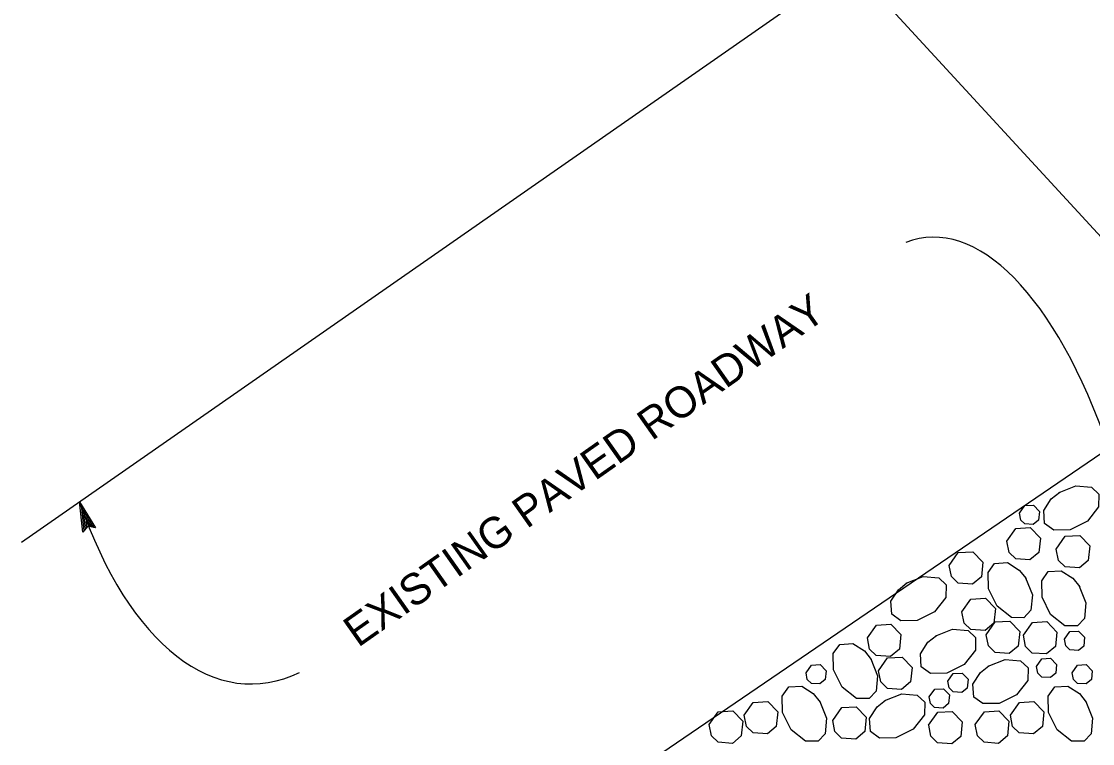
# Model space of a CAD drawing. Extents: x 6709491 to 6710959, y 1869789 to 1870763.
# Drawn here: x 6709490.8 to 6709696.9, y 1870298.5 to 1870437.5 of the extents above; entities that cross this region are included whole.
import ezdxf

# ---------------------------------------------------------------- set-up
doc = ezdxf.new("R2010")
doc.units = 0
for name, color, linetype in [('56 Stg 3 Anno', 7, 'Continuous'), ('57 Undefined', 7, 'Continuous'), ('60 Nongeo Data', 7, 'Continuous')]:
    doc.layers.add(name, color=color, linetype=linetype)

msp = doc.modelspace()

# ---------------------------------------------------------------- linework, layer by layer
at = {"layer": '56 Stg 3 Anno'}
for p, q in [((6709720.74, 1870371.76), (6709642.2, 1870457.23)), ((6709502.63, 1870339.17), (6709501.98, 1870345.03)), ((6709501.98, 1870345.03), (6709501.98, 1870345.03)), ((6709501.98, 1870345.03), (6709505.05, 1870340)), ((6709502.89, 1870339.48), (6709502.41, 1870343.78)), ((6709502.41, 1870343.77), (6709504.66, 1870340.1)), ((6709503.14, 1870339.8), (6709502.84, 1870342.52)), ((6709502.84, 1870342.52), (6709504.28, 1870340.16)), ((6709503.6, 1870340.31), (6709502.63, 1870339.17)), ((6709503.4, 1870340.07), (6709503.27, 1870341.27)), ((6709503.27, 1870341.27), (6709503.89, 1870340.26)), ((6709505.05, 1870340), (6709503.6, 1870340.31)), ((6709505.05, 1870340), (6709505.05, 1870340)), ((6709502.63, 1870339.17), (6709502.63, 1870339.17))]:
    msp.add_line(p, q, dxfattribs=at)
for centre, major_axis, ratio, start_param, end_param in [((6709673.96, 1870309.82), (9.19, -86.07), 0.406988, 2.083758, 3.252367), ((6709534.98, 1870392.41), (0, 82.45), 0.489041, 2.182883, 3.375209)]:
    msp.add_ellipse(centre, major_axis=major_axis, ratio=ratio, start_param=start_param, end_param=end_param, dxfattribs=at)
at = {"layer": '60 Nongeo Data'}
for p, q in [((6709490.8, 1870337.24), (6709770.14, 1870531.99)), ((6709495.94, 1870216.26), (6709884.38, 1870481.01))]:
    msp.add_line(p, q, dxfattribs=at)
for points in [[(6709690.41, 1870346.81), (6709693.66, 1870348.1), (6709696.65, 1870347.85), (6709698.07, 1870346.5), (6709698.03, 1870344.07), (6709695.87, 1870341.31), (6709692.54, 1870339.65), (6709689.4, 1870339.59), (6709687.63, 1870340.85), (6709687.46, 1870343.35), (6709688.9, 1870345.59), (6709690.54, 1870346.9)], [(6709682.78, 1870342.81), (6709683.83, 1870344.29), (6709685.49, 1870344.39), (6709686.65, 1870343.19), (6709686.49, 1870341.51), (6709685.46, 1870340.65), (6709683.81, 1870340.77), (6709683.04, 1870341.52), (6709682.79, 1870342.81)], [(6709680.37, 1870337.43), (6709682.11, 1870339.9), (6709684.89, 1870340.06), (6709686.82, 1870338.06), (6709686.54, 1870335.26), (6709684.82, 1870333.83), (6709682.08, 1870334.03), (6709680.79, 1870335.28), (6709680.37, 1870337.43)], [(6709689.88, 1870335.91), (6709691.62, 1870338.39), (6709694.4, 1870338.55), (6709696.33, 1870336.54), (6709696.05, 1870333.74), (6709694.33, 1870332.31), (6709691.59, 1870332.51), (6709690.3, 1870333.76), (6709689.88, 1870335.91)], [(6709669.3, 1870332.78), (6709671.04, 1870335.26), (6709673.81, 1870335.42), (6709675.74, 1870333.41), (6709675.47, 1870330.61), (6709673.75, 1870329.18), (6709671.01, 1870329.38), (6709669.72, 1870330.63), (6709669.3, 1870332.78)], [(6709683.99, 1870330.38), (6709685.28, 1870327.13), (6709685.02, 1870324.14), (6709683.67, 1870322.72), (6709681.25, 1870322.76), (6709678.49, 1870324.92), (6709676.83, 1870328.25), (6709676.77, 1870331.39), (6709678.03, 1870333.16), (6709680.53, 1870333.33), (6709682.76, 1870331.89), (6709684.07, 1870330.25)], [(6709694.3, 1870328.8), (6709695.59, 1870325.55), (6709695.34, 1870322.56), (6709693.98, 1870321.14), (6709691.56, 1870321.18), (6709688.8, 1870323.34), (6709687.14, 1870326.67), (6709687.08, 1870329.81), (6709688.34, 1870331.58), (6709690.84, 1870331.75), (6709693.08, 1870330.31), (6709694.39, 1870328.67)], [(6709661.02, 1870329.34), (6709664.27, 1870330.62), (6709667.26, 1870330.37), (6709668.68, 1870329.02), (6709668.64, 1870326.59), (6709666.48, 1870323.83), (6709663.15, 1870322.17), (6709660.01, 1870322.11), (6709658.24, 1870323.37), (6709658.07, 1870325.87), (6709659.51, 1870328.11), (6709661.15, 1870329.42)], [(6709671.72, 1870323.84), (6709673.46, 1870326.31), (6709676.24, 1870326.47), (6709678.17, 1870324.47), (6709677.89, 1870321.66), (6709676.18, 1870320.24), (6709673.43, 1870320.43), (6709672.14, 1870321.69), (6709671.73, 1870323.84)], [(6709653.55, 1870318.83), (6709655.29, 1870321.3), (6709658.06, 1870321.46), (6709659.99, 1870319.46), (6709659.71, 1870316.65), (6709658, 1870315.23), (6709655.26, 1870315.43), (6709653.97, 1870316.68), (6709653.55, 1870318.83)], [(6709676.4, 1870319.43), (6709678.14, 1870321.91), (6709680.92, 1870322.06), (6709682.85, 1870320.06), (6709682.57, 1870317.26), (6709680.85, 1870315.83), (6709678.11, 1870316.03), (6709676.82, 1870317.28), (6709676.4, 1870319.43)], [(6709683.55, 1870319.33), (6709685.29, 1870321.8), (6709688.07, 1870321.96), (6709690, 1870319.96), (6709689.72, 1870317.15), (6709688.01, 1870315.73), (6709685.26, 1870315.92), (6709683.97, 1870317.18), (6709683.56, 1870319.33)], [(6709666.7, 1870319.21), (6709669.95, 1870320.5), (6709672.94, 1870320.24), (6709674.36, 1870318.89), (6709674.32, 1870316.46), (6709672.16, 1870313.7), (6709668.83, 1870312.04), (6709665.69, 1870311.98), (6709663.92, 1870313.24), (6709663.75, 1870315.74), (6709665.19, 1870317.98), (6709666.83, 1870319.29)], [(6709691.47, 1870318.56), (6709692.51, 1870320.05), (6709694.18, 1870320.14), (6709695.34, 1870318.94), (6709695.17, 1870317.26), (6709694.14, 1870316.4), (6709692.49, 1870316.52), (6709691.72, 1870317.27), (6709691.47, 1870318.56)], [(6709654.21, 1870314.81), (6709655.5, 1870311.55), (6709655.25, 1870308.56), (6709653.89, 1870307.14), (6709651.47, 1870307.19), (6709648.71, 1870309.35), (6709647.05, 1870312.68), (6709646.99, 1870315.82), (6709648.25, 1870317.58), (6709650.75, 1870317.75), (6709652.99, 1870316.32), (6709654.3, 1870314.67)], [(6709655.69, 1870312.52), (6709657.43, 1870314.99), (6709660.21, 1870315.15), (6709662.14, 1870313.15), (6709661.86, 1870310.34), (6709660.14, 1870308.92), (6709657.4, 1870309.12), (6709656.11, 1870310.37), (6709655.69, 1870312.52)], [(6709686.09, 1870313.34), (6709687.13, 1870314.83), (6709688.79, 1870314.92), (6709689.95, 1870313.72), (6709689.79, 1870312.04), (6709688.76, 1870311.18), (6709687.11, 1870311.3), (6709686.34, 1870312.05), (6709686.09, 1870313.34)], [(6709641.74, 1870312.12), (6709642.79, 1870313.6), (6709644.45, 1870313.7), (6709645.61, 1870312.5), (6709645.44, 1870310.81), (6709644.42, 1870309.96), (6709642.77, 1870310.08), (6709641.99, 1870310.83), (6709641.74, 1870312.12)], [(6709676.79, 1870313.39), (6709680.05, 1870314.68), (6709683.03, 1870314.42), (6709684.46, 1870313.07), (6709684.41, 1870310.65), (6709682.25, 1870307.89), (6709678.92, 1870306.23), (6709675.78, 1870306.17), (6709674.01, 1870307.43), (6709673.85, 1870309.93), (6709675.28, 1870312.17), (6709676.92, 1870313.48)], [(6709692.94, 1870312.12), (6709693.98, 1870313.6), (6709695.65, 1870313.7), (6709696.81, 1870312.5), (6709696.64, 1870310.81), (6709695.61, 1870309.96), (6709693.96, 1870310.08), (6709693.19, 1870310.83), (6709692.94, 1870312.12)], [(6709669.04, 1870310.49), (6709670.08, 1870311.97), (6709671.75, 1870312.07), (6709672.91, 1870310.87), (6709672.74, 1870309.18), (6709671.71, 1870308.33), (6709670.06, 1870308.45), (6709669.29, 1870309.2), (6709669.04, 1870310.49)], [(6709644.37, 1870306.6), (6709645.66, 1870303.35), (6709645.4, 1870300.36), (6709644.05, 1870298.94), (6709641.63, 1870298.98), (6709638.87, 1870301.14), (6709637.21, 1870304.47), (6709637.15, 1870307.61), (6709638.41, 1870309.38), (6709640.91, 1870309.54), (6709643.14, 1870308.11), (6709644.46, 1870306.47)], [(6709665.45, 1870307.47), (6709666.49, 1870308.95), (6709668.16, 1870309.05), (6709669.32, 1870307.85), (6709669.15, 1870306.17), (6709668.12, 1870305.31), (6709666.48, 1870305.43), (6709665.7, 1870306.18), (6709665.45, 1870307.47)], [(6709695.56, 1870306.6), (6709696.86, 1870303.35), (6709696.6, 1870300.36), (6709695.25, 1870298.94), (6709692.82, 1870298.98), (6709690.06, 1870301.14), (6709688.4, 1870304.47), (6709688.34, 1870307.61), (6709689.6, 1870309.38), (6709692.1, 1870309.54), (6709694.34, 1870308.11), (6709695.65, 1870306.47)], [(6709656.91, 1870306.76), (6709660.16, 1870308.05), (6709663.15, 1870307.8), (6709664.57, 1870306.44), (6709664.53, 1870304.02), (6709662.37, 1870301.26), (6709659.04, 1870299.6), (6709655.9, 1870299.54), (6709654.13, 1870300.8), (6709653.96, 1870303.3), (6709655.4, 1870305.54), (6709657.04, 1870306.85)], [(6709623.11, 1870302.13), (6709624.85, 1870304.61), (6709627.63, 1870304.77), (6709629.56, 1870302.77), (6709629.28, 1870299.96), (6709627.57, 1870298.53), (6709624.82, 1870298.73), (6709623.53, 1870299.98), (6709623.12, 1870302.13)], [(6709629.86, 1870303.95), (6709631.6, 1870306.42), (6709634.38, 1870306.58), (6709636.31, 1870304.58), (6709636.03, 1870301.78), (6709634.31, 1870300.35), (6709631.57, 1870300.55), (6709630.28, 1870301.8), (6709629.86, 1870303.95)], [(6709646.88, 1870302.95), (6709648.62, 1870305.42), (6709651.39, 1870305.58), (6709653.32, 1870303.58), (6709653.04, 1870300.78), (6709651.33, 1870299.35), (6709648.59, 1870299.55), (6709647.3, 1870300.8), (6709646.88, 1870302.95)], [(6709665.33, 1870302.03), (6709667.07, 1870304.51), (6709669.85, 1870304.67), (6709671.78, 1870302.66), (6709671.5, 1870299.86), (6709669.79, 1870298.43), (6709667.04, 1870298.63), (6709665.75, 1870299.88), (6709665.34, 1870302.03)], [(6709674.31, 1870302.13), (6709676.05, 1870304.61), (6709678.83, 1870304.77), (6709680.76, 1870302.77), (6709680.48, 1870299.96), (6709678.76, 1870298.53), (6709676.02, 1870298.73), (6709674.73, 1870299.98), (6709674.31, 1870302.13)], [(6709681.05, 1870303.95), (6709682.79, 1870306.42), (6709685.57, 1870306.58), (6709687.5, 1870304.58), (6709687.22, 1870301.78), (6709685.51, 1870300.35), (6709682.76, 1870300.55), (6709681.47, 1870301.8), (6709681.06, 1870303.95)]]:
    msp.add_lwpolyline(points, dxfattribs=at)

# ---------------------------------------------------------------- texts
at = {"layer": '57 Undefined'}
msp.add_text('EXISTING PAVED ROADWAY', height=6, rotation=35.1601, dxfattribs=at).set_placement((6709555.57, 1870316.88))

doc.saveas('drawing.dxf')
